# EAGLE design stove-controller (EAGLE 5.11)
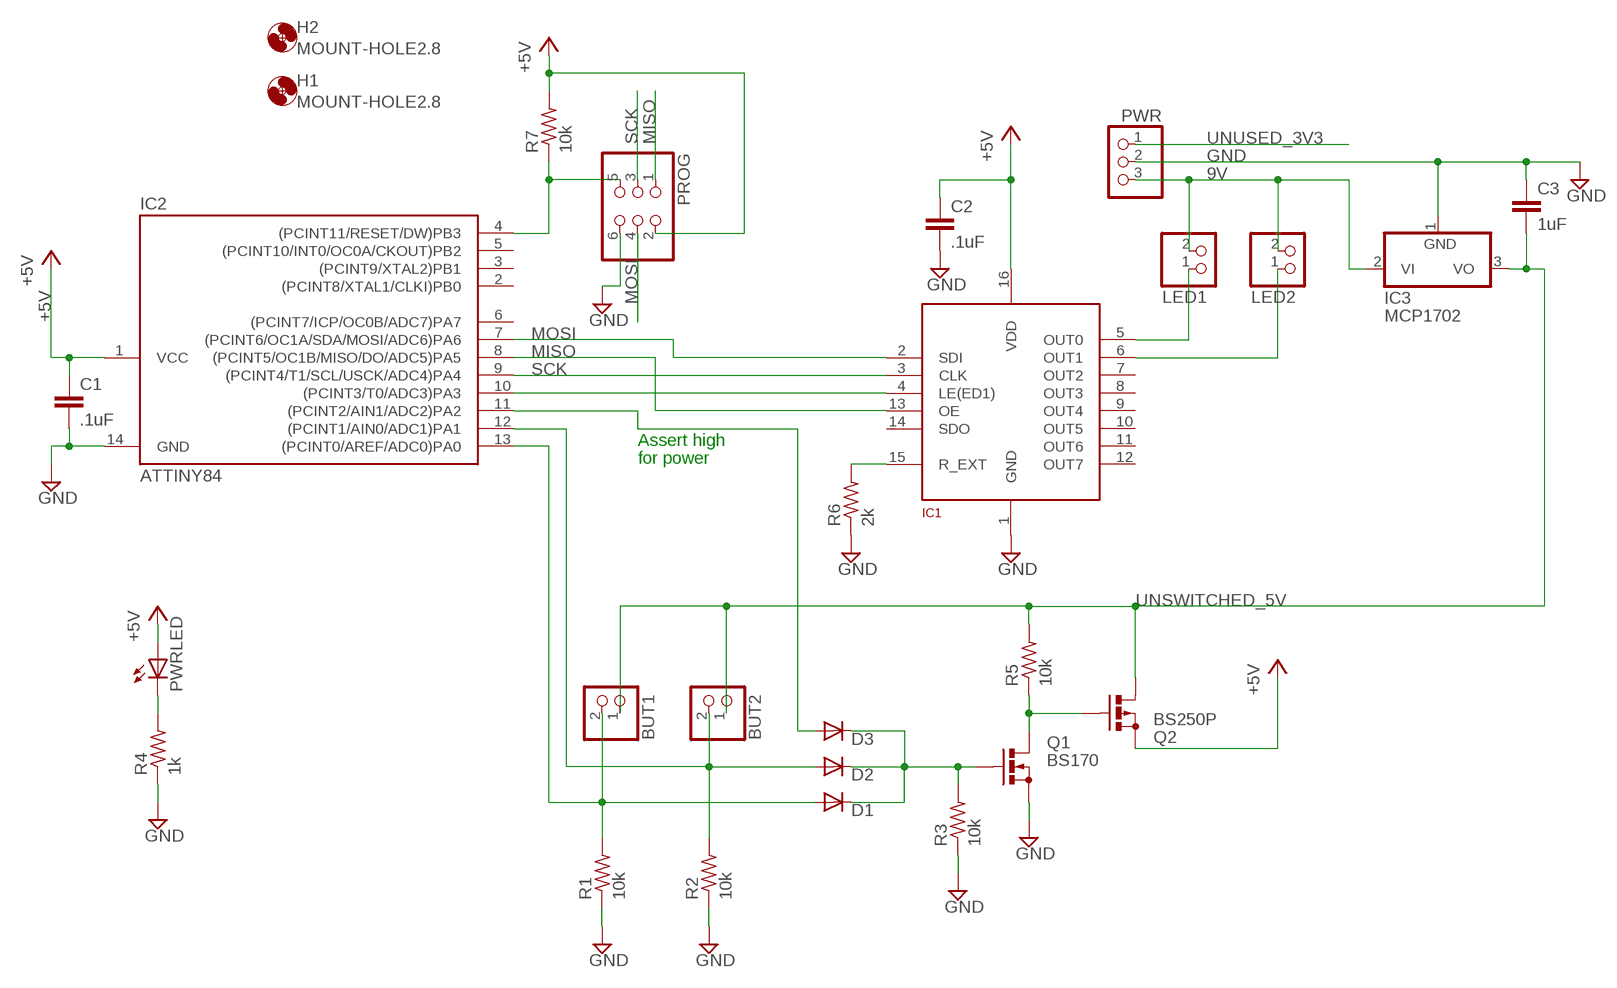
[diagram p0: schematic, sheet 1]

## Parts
BUT1  PINHD-1X2/90  [1X02/90]
BUT2  PINHD-1X2/90  [1X02/90]
C1  .1uF  C5/5  [C5B5]
C2  .1uF  C5/5  [C5B5]
C3  1uF  C5/5  [C5B5]
D1  1N4148DO35-7  [DO35-7]
D2  1N4148DO35-7  [DO35-7]
D3  1N4148DO35-7  [DO35-7]
H1  MOUNT-HOLE2.8  [2,8]
H2  MOUNT-HOLE2.8  [2,8]
IC1  TLC5916/17DIP  [DIP-16]
IC2  ATTINY84  TINY24/44/84-PU  [DIL14]
IC3  MCP1702  7905L  [TO92]
LED1  PINHD-1X2/90  [1X02/90]
LED2  PINHD-1X2/90  [1X02/90]
PROG  PINHD-2X3  [2X03]
PWR  PINHD-1X3/90  [1X03/90]
PWRLED  LED5MM  [LED5MM]
Q1  BS170  [SOT54E]
Q2  BS250P  BS250  [SOT54E]
R1  10k  R-US_0204/5  [0204/5]
R2  10k  R-US_0204/5  [0204/5]
R3  10k  R-US_0204/5  [0204/5]
R4  1k  R-US_0204/5  [0204/5]
R5  10k  R-US_0204/5  [0204/5]
R6  2k  R-US_0204/5  [0204/5]
R7  10k  R-US_0204/5  [0204/5]

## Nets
9V [power]: IC3.2(VI) LED1.2 LED2.2 PWR.3
+5V [power]: C1.1 C2.1 IC1.16(VDD) IC2.1(VCC) PROG.2 PWRLED.A Q2.S R7.2
GND: C1.2 C2.2 C3.1 IC1.1(GND) IC2.14(GND) IC3.1(GND) PROG.6 PWR.2 Q1.S R1.1 R2.1 R3.1 R4.1 R6.1
MISO: IC1.13(OE) IC2.8((PCINT5/OC1B/MISO/DO/ADC5)PA5) PROG.1
MOSI: IC1.2(SDI) IC2.7((PCINT6/OC1A/SDA/MOSI/ADC6)PA6) PROG.4
N$1 [power]: IC1.6(OUT1) LED2.1
N$2 [power]: IC1.5(OUT0) LED1.1
N$5: IC1.4(LE(ED1)) IC2.10((PCINT3/T0/ADC3)PA3)
N$6: IC1.15(R_EXT) R6.2
N$7: Q1.D Q2.G R5.1
N$8: D1.C D2.C D3.C Q1.G R3.2
N$9: D3.A IC2.11((PCINT2/AIN1/ADC2)PA2)
N$10: BUT1.2 D1.A IC2.13((PCINT0/AREF/ADC0)PA0) R1.2
N$14: BUT2.2 D2.A IC2.12((PCINT1/AIN0/ADC1)PA1) R2.2
PWRLED: PWRLED.K(C) R4.2
RESET: IC2.4((PCINT11/RESET/DW)PB3) PROG.5 R7.1
SCK: IC1.3(CLK) IC2.9((PCINT4/T1/SCL/USCK/ADC4)PA4) PROG.3
UNSWITCHED_5V [power]: BUT1.1 BUT2.1 C3.2 IC3.3(VO) Q2.D R5.2
UNUSED_3V3: PWR.1
Unconnected: IC1.7(OUT2) IC1.8(OUT3) IC1.9(OUT4) IC1.10(OUT5) IC1.11(OUT6) IC1.12(OUT7) IC1.14(SDO) IC2.2((PCINT8/XTAL1/CLKI)PB0) IC2.3((PCINT9/XTAL2)PB1) IC2.5((PCINT10/INT0/OC0A/CKOUT)PB2) IC2.6((PCINT7/ICP/OC0B/ADC7)PA7)

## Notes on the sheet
- Assert high
- for power

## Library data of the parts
BUT1 BUT2 LED1 LED2 = pinhead:PINHD-1X2: PIN HEADER
C1-C3 = capacitor-wima:C: CAPACITOR
D1-D3 = diode:1N4148: DIODE
H1 H2 = holes:MOUNT-HOLE: MOUNTING HOLE with drill center marker
IC1 = BillPorter:TLC5916/17: TLC5916/17 8-Channel Constant-Current LED Sink Driver and Shift Register in one. Great for driving high current LEDs that would kill a 595 shift register. Specs @ http://focus.ti.com/docs/prod/folders/print/tlc5916.html
IC2 = avr-4:TINY24/44/84
IC3 = linear:79*: Negative VOLTAGE REGULATOR
PROG = pinhead:PINHD-2X3: PIN HEADER
PWR = pinhead:PINHD-1X3: PIN HEADER
PWRLED = led:LED: LED
Q1 = transistor-small-signal:BS170: N-CHANNEL MOS FET
Q2 = transistor-small-signal:BS250: P-CHANNEL MOS FET
R1-R7 = rcl:R-US_: RESISTOR, American symbol

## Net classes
1 power: width 0.508 mm

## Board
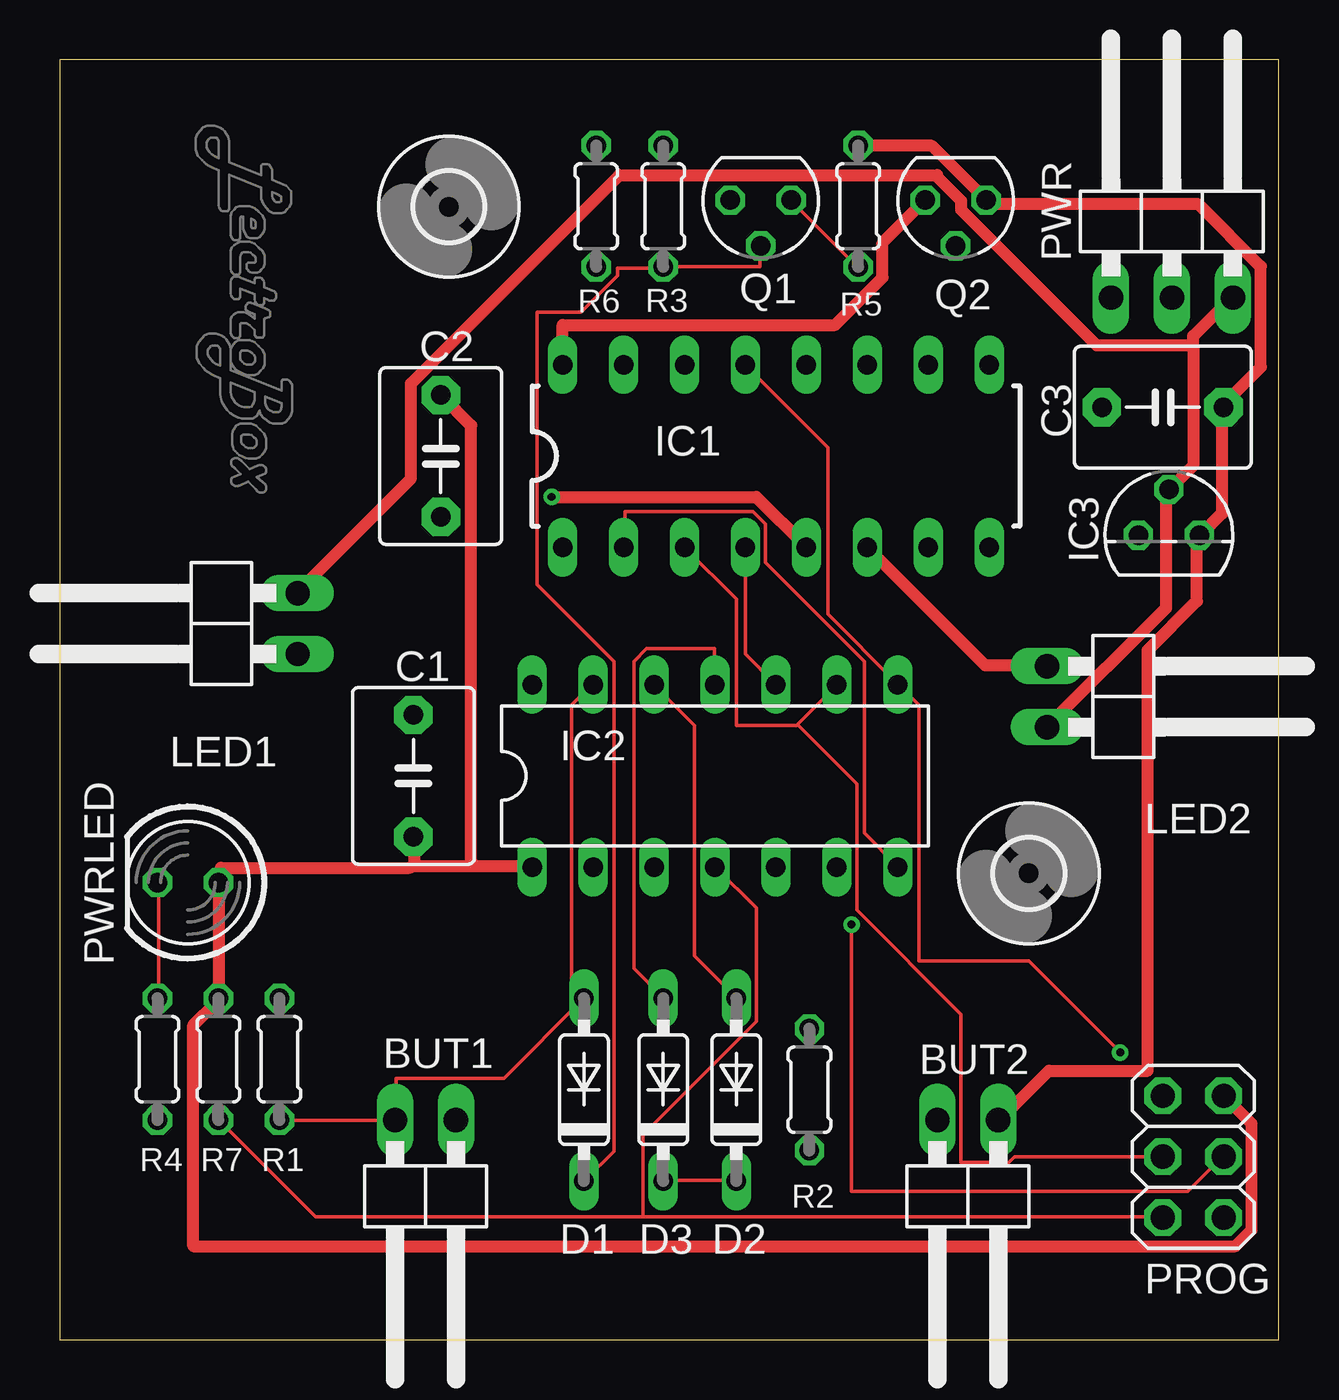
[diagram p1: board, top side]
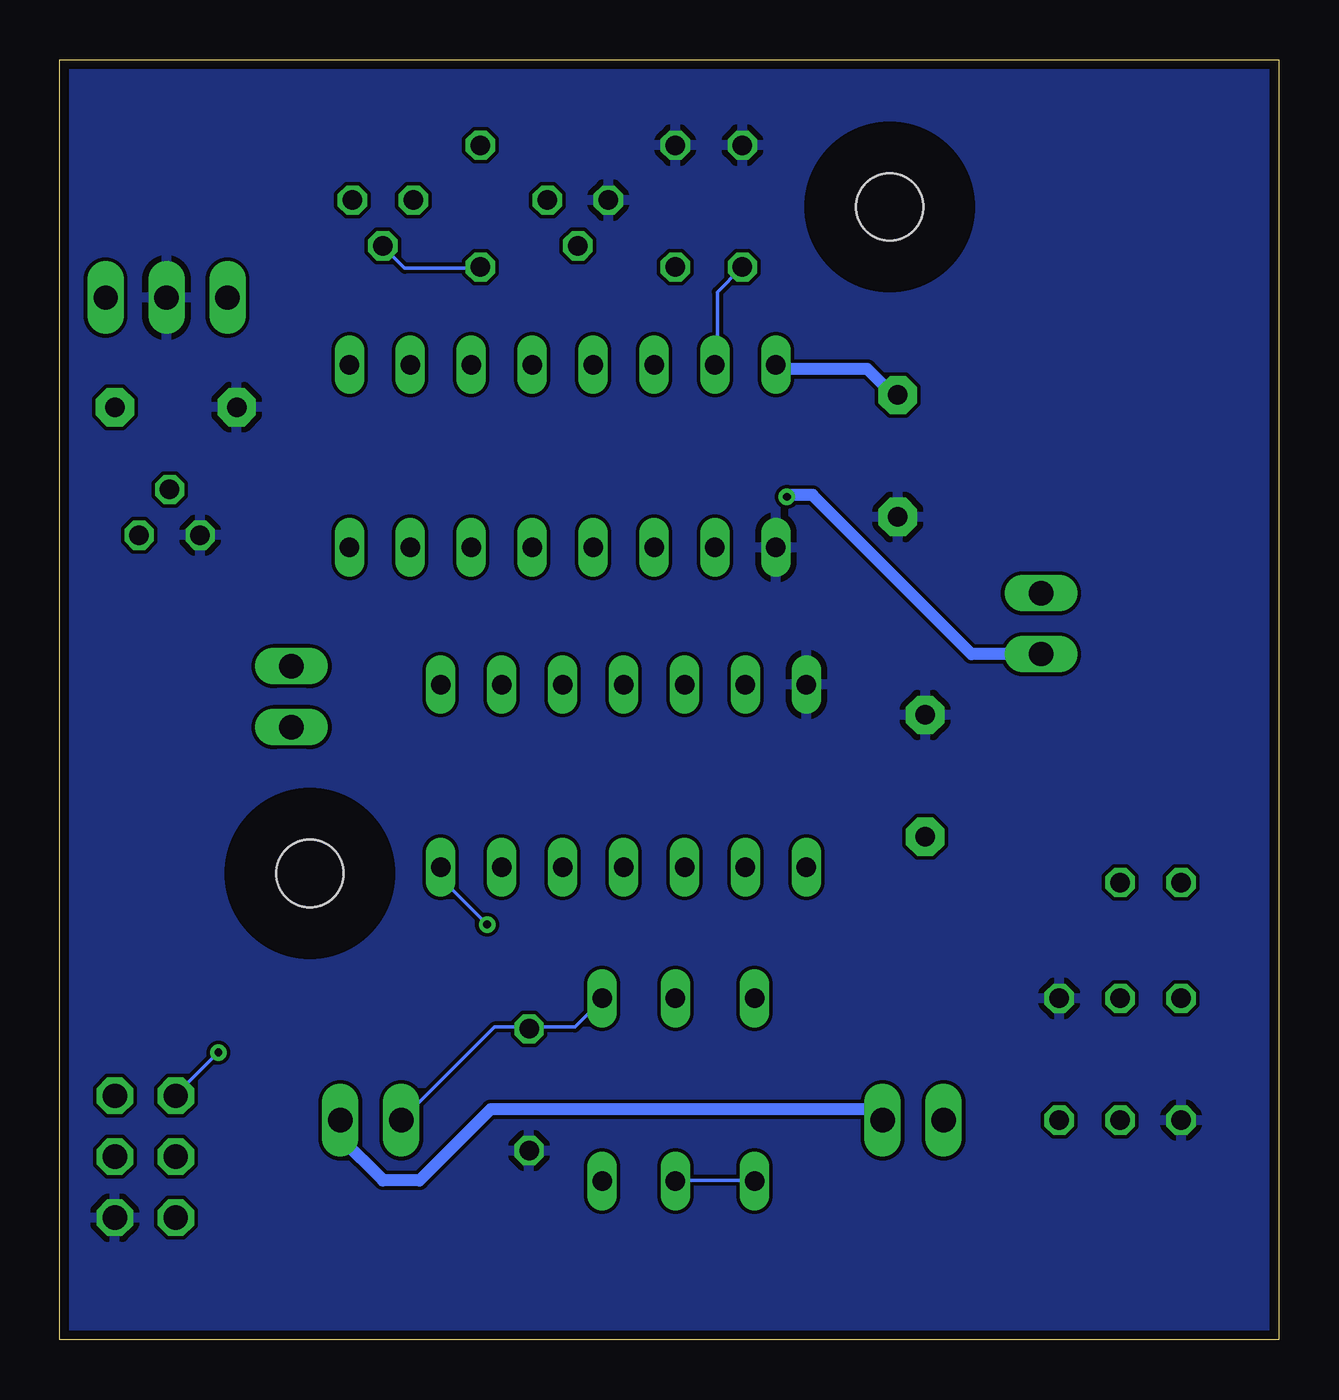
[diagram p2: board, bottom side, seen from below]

Size 50.8 x 53.34 mm. Coordinates in mm from the lower left corner, seen from the top.
Outline: 0,0 50.8,0 50.8,53.34 0,53.34 0,0
Copper layers (1*16): Top 0.0356mm / dielectric 1.5011mm / Bottom 0.0356mm
Design rules "LaenPCBOrder": minimum track width 6mil, minimum drill 13mil, track to track 6mil, track to pad 6mil, pad to pad 6mil, via to via 6mil, smd to smd 6mil, copper to edge 15mil, drill to drill 6mil, minimum pad ring 7mil, minimum via ring 7mil, stop-mask expansion 4mil, vias tented up to drill 0mil, thermal gap 10mil
tRestrict: area 45.2,8.6 to 46.7,9.1

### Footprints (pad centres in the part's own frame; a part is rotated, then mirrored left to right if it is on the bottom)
1X02/90 = drill 1.016 long: 1 -1.27,-3.81; 2 1.27,-3.81
C5B5 = drill 0.813 pad 1.6 octagon: 1 -2.54,0; 2 2.54,0
DO35-7 = drill 0.813 long: A 3.81,0; C -3.81,0
2,8 = hole 2.8: 0,0
DIP-16 = drill 0.813 long: 1 -8.89,-3.81; 2 -6.35,-3.81; 3 -3.81,-3.81; 4 -1.27,-3.81; 5 1.27,-3.81; 6 3.81,-3.81; 7 6.35,-3.81; 8 8.89,-3.81; 9 8.89,3.81; 10 6.35,3.81; 11 3.81,3.81; 12 1.27,3.81; 13 -1.27,3.81; 14 -3.81,3.81; 15 -6.35,3.81; 16 -8.89,3.81
DIL14 = drill 0.813 long: 1 -7.62,-3.81; 2 -5.08,-3.81; 3 -2.54,-3.81; 4 0,-3.81; 5 2.54,-3.81; 6 5.08,-3.81; 7 7.62,-3.81; 8 7.62,3.81; 9 5.08,3.81; 10 2.54,3.81; 11 0,3.81; 12 -2.54,3.81; 13 -5.08,3.81; 14 -7.62,3.81
TO92 = drill 0.813 octagon: 1 -1.27,0; 2 0,1.905; 3 1.27,0
2X03 = drill 1.016 octagon: 1 -2.54,-1.27; 2 -2.54,1.27; 3 0,-1.27; 4 0,1.27; 5 2.54,-1.27; 6 2.54,1.27
1X03/90 = drill 1.016 long: 1 -2.54,-3.81; 2 0,-3.81; 3 2.54,-3.81
LED5MM = drill 0.813 octagon: A -1.27,0; K 1.27,0
SOT54E = drill 0.813 octagon: D -1.27,0; G 0,1.905; S 1.27,0
0204/5 = drill 0.813 octagon: 1 -2.54,0; 2 2.54,0

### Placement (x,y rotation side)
BUT1  15.24,5.33 180 top
BUT2  37.85,5.33 180 top
C1  14.73,23.5 90 top
C2  15.88,36.83 270 top
C3  45.97,38.86 0 top
D1  21.84,10.41 90 top
D2  28.19,10.41 90 top
D3  25.15,10.41 90 top
H1  40.39,19.43 0 top
H2  16.21,47.22 0 top
IC1  29.84,36.83 0 top
IC2  27.3,23.5 0 top
IC3  46.23,33.53 0 top
LED1  6.1,29.84 90 top
LED2  44.96,26.8 270 top
PROG  47.24,7.62 270 top
PWR  46.35,47.24 0 top
PWRLED  5.33,19.05 180 top
Q1  29.21,47.5 180 top
Q2  37.34,47.5 180 top
R1  9.14,11.68 270 top
R2  31.24,10.41 90 top
R3  25.15,47.24 270 top
R4  4.06,11.68 90 top
R5  33.27,47.24 90 top
R6  22.35,47.24 270 top
R7  6.6,11.68 90 top

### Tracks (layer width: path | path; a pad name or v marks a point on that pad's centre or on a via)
9V
  Top 0.508: 47.24,41.45 47.24,41.83 48.84,43.43 PWR.3 | 47.24,41.45 47.24,36.42 46.25,35.43 IC3.2 46.1,35.2 46.1,30.48 LED2.2 | LED1.2 9.91,31.17 14.63,35.89 14.63,39.85 23.32,48.54 36.58,48.54 36.58,48.46 37.57,47.47 37.57,47.09 43.2,41.45 47.02,41.45 47.24,41.45
+5V
  Top 0.508: Q2.S 36.04,47.47 34.29,45.72 34.29,44.27 32.31,42.29 20.95,42.29 20.95,40.69 IC1.16 | 14.78,19.74 17.14,19.74 | 17.14,19.74 19.66,19.74 IC2.1 | 14.78,19.74 14.78,20.95 C1.1 | PROG.2 48.54,10.13 49.68,8.99 49.68,4.57 49,3.89 5.56,3.89 5.56,13.11 6.48,14.02 R7.2 6.63,14.25 6.63,19.05 PWRLED.A 6.71,19.28 6.71,19.66 14.55,19.66 14.78,19.74 | C2.1 15.93,39.32 17.14,38.1 17.14,19.96 17.14,19.74
  Bottom 0.508: IC1.16 20.95,40.62 20.8,40.46 17.14,40.46 16.08,39.4 15.93,39.4 C2.1
GND
  pour Bottom: 50.75,53.14 50.75,0.07 0.23,0.07 0.26,53.03
MISO  (via drill 0.33)
  Top 0.152: IC1.13 28.57,40.62 32,37.19 32,30.25 34.9,27.36 IC2.8 34.98,27.28 35.81,26.44 35.81,15.77 40.39,15.77 v44.2,11.96
  Bottom 0.152: v44.2,11.96 45.95,10.21 PROG.1
MOSI  (via drill 0.33)
  Top 0.152: IC2.7 34.9,19.74 33.53,21.11 33.53,28.27 29.41,32.38 29.41,33.98 28.88,34.52 23.55,34.52 23.55,33.07 IC1.2 | v32.99,17.3 32.99,6.17 47.02,6.17 48.46,7.62 PROG.4
  Bottom 0.152: v32.99,17.3 34.9,19.2 34.9,19.66 IC2.7
N$1
  Top 0.508: IC1.6 33.68,32.99 38.56,28.12 41.15,28.12 LED2.1
N$2  (via drill 0.33)
  Top 0.508: v20.5,35.13 29.03,35.13 31.09,33.07 IC1.5
  Bottom 0.508: v20.5,35.13 20.42,35.2 19.43,35.2 12.8,28.57 LED1.1
N$5
  Top 0.152: IC2.10 29.79,27.36 28.57,28.57 28.57,32.99 IC1.4
N$6
  Bottom 0.152: R6.2 22.4,44.65 23.39,43.66 23.39,40.69 23.47,40.69 IC1.15
N$7
  Top 0.152: Q1.D 30.48,47.47 33.22,44.73 R5.1
  Bottom 0.152: Q2.G 37.34,45.57 36.42,44.65 33.3,44.65 R5.1
N$8
  Top 0.152: Q1.G 29.18,45.57 29.18,44.73 25.15,44.73 R3.2 25.15,44.65 23.24,44.65 23.24,44.35 21.72,42.82 19.89,42.82 19.89,31.47 23.09,28.27 23.09,7.85 21.87,6.63 D1.C | D2.C 28.19,6.63 25.15,6.63 D3.C
  Bottom 0.152: D1.C 21.87,6.63 25.15,6.63 D3.C
N$9
  Top 0.152: D3.A 25.15,14.25 23.93,15.47 23.93,28.27 24.46,28.8 27.28,28.8 27.28,27.36 IC2.11
N$10
  Top 0.152: R1.2 13.95,9.14 BUT1.2 14.02,9.14 14.02,10.9 18.52,10.9 21.79,14.17 D1.A 21.34,13.79 21.34,26.44 22.17,27.28 IC2.13
N$14
  Top 0.152: IC2.12 24.77,27.28 26.44,25.6 26.44,16 28.19,14.25 D2.A
  Bottom 0.152: D2.A 28.19,14.17 29.34,13.03 31.17,13.03 R2.2 31.24,13.03 32.69,13.03 BUT2.2
PWRLED
  Top 0.152: R4.2 4.12,14.25 4.12,19.05 PWRLED.K
RESET
  Top 0.152: 24.31,5.11 10.67,5.11 6.63,9.14 R7.1 | 24.31,5.11 24.31,8.53 29.03,13.26 29.03,17.98 27.36,19.66 IC2.4 | 24.31,5.11 45.95,5.11 PROG.5
SCK
  Top 0.152: 30.75,25.64 30.71,25.6 28.19,25.6 28.19,30.86 26.06,32.99 IC1.3 | 30.75,25.64 32.38,27.28 IC2.9 | PROG.3 45.95,7.62 39.78,7.62 39.55,7.39 37.57,7.39 37.57,13.56 33.22,17.91 33.22,23.16 30.79,25.6 30.75,25.64
UNSWITCHED_5V
  Top 0.508: R5.2 33.3,49.76 36.35,49.76 38.56,47.55 Q2.D 38.79,47.32 47.47,47.32 50.06,44.73 50.06,40.54 48.62,39.09 C3.2 48.46,38.86 48.46,34.44 47.55,33.53 IC3.3 47.4,33.3 47.4,30.79 45.34,28.73 45.34,11.2 41.22,11.2 39.17,9.14 BUT2.1
  Bottom 0.508: BUT1.1 16.54,9.14 16.99,9.6 32.84,9.6 35.81,6.63 37.34,6.63 39.09,8.38 39.09,9.14 BUT2.1

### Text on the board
tDocu: Battery Saver Rev. B | Ikea Duktig Play Stove | 1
